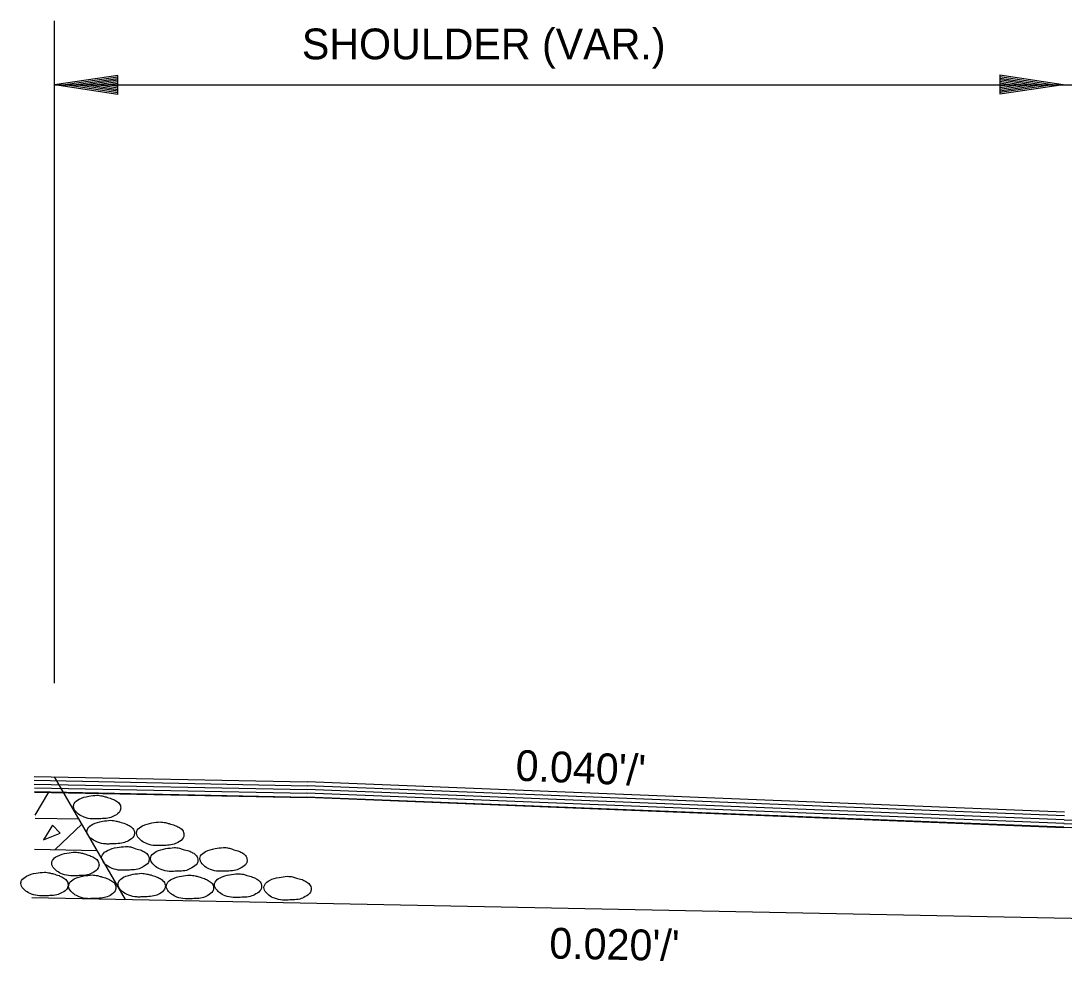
# Model space of a CAD drawing. Extents: x 1926836 to 1933254, y 596317 to 604524.
# Drawn here: x 1928421.2 to 1928623.7, y 602598.8 to 602781.4 of the extents above; entities that cross this region are included whole.
import ezdxf

# ---------------------------------------------------------------- set-up
doc = ezdxf.new("R2010")
doc.units = 0
doc.layers.add('Default', color=7, linetype='Continuous')

msp = doc.modelspace()

# ---------------------------------------------------------------- linework, layer by layer
at = {"layer": 'Default'}
for p, q in [((1928427.69, 602652.78), (1928427.69, 602781.38)), ((1928439.97, 602770.77), (1928427.69, 602768.94)), ((1928439.97, 602770.46), (1928429.75, 602768.94)), ((1928439.97, 602770.14), (1928431.86, 602768.94)), ((1928439.97, 602769.84), (1928433.92, 602768.94)), ((1928439.97, 602769.52), (1928435.98, 602768.94)), ((1928439.97, 602769.21), (1928438.03, 602768.94)), ((1928439.97, 602767.07), (1928439.97, 602770.77)), ((1928611.19, 602770.9), (1928623.46, 602769.03)), ((1928611.19, 602770.9), (1928611.19, 602767.2)), ((1928611.19, 602770.58), (1928621.4, 602769.03)), ((1928611.19, 602770.26), (1928619.3, 602769.03)), ((1928611.19, 602769.97), (1928617.24, 602769.03)), ((1928611.19, 602769.65), (1928615.18, 602769.03)), ((1928611.19, 602769.33), (1928613.12, 602769.03)), ((1928427.69, 602768.94), (1928756.85, 602768.94)), ((1928439.97, 602767.07), (1928427.69, 602768.94)), ((1928439.97, 602767.39), (1928429.75, 602768.94)), ((1928439.97, 602767.71), (1928431.86, 602768.94)), ((1928439.97, 602768.01), (1928433.92, 602768.94)), ((1928439.97, 602768.32), (1928435.98, 602768.94)), ((1928439.97, 602768.64), (1928438.03, 602768.94)), ((1928611.19, 602767.2), (1928623.46, 602769.03)), ((1928611.19, 602768.45), (1928615.18, 602769.03)), ((1928611.19, 602767.83), (1928619.3, 602769.03)), ((1928611.19, 602767.52), (1928621.4, 602769.03)), ((1928611.19, 602768.13), (1928617.24, 602769.03)), ((1928611.19, 602768.77), (1928613.12, 602769.03)), ((1928423.75, 602634.69), (1928476.7, 602633.64)), ((1928423.75, 602633.96), (1928476.7, 602632.9)), ((1928441.46, 602610.8), (1928427.69, 602634.61)), ((1928623.71, 602627.76), (1928476.7, 602633.64)), ((1928423.77, 602633.22), (1928476.7, 602632.17)), ((1928423.8, 602632.49), (1928476.7, 602631.43)), ((1928423.82, 602631.75), (1928476.65, 602630.7)), ((1928423.82, 602631.65), (1928476.7, 602630.6)), ((1928423.92, 602627.19), (1928426.57, 602631.63)), ((1928623.66, 602626.29), (1928476.65, 602632.17)), ((1928623.66, 602625.55), (1928476.65, 602631.43)), ((1928623.71, 602627.02), (1928476.7, 602632.9)), ((1928623.61, 602624.82), (1928476.6, 602630.7)), ((1928623.61, 602624.72), (1928476.7, 602630.6)), ((1928423.95, 602626.61), (1928432.42, 602626.44)), ((1928427.79, 602620.51), (1928433, 602625.43)), ((1928623.61, 602625.55), (1928757.71, 602620.19)), ((1928623.64, 602626.29), (1928757.74, 602620.92)), ((1928623.58, 602624.82), (1928757.68, 602619.45)), ((1928423.82, 602620.59), (1928435.94, 602620.34)), ((1928423.27, 602611.17), (1928815.02, 602603.38))]:
    msp.add_line(p, q, dxfattribs=at)
msp.add_lwpolyline([(1928425.55, 602622.36), (1928428.78, 602623.68), (1928427.31, 602625.25), (1928425.55, 602622.36)], dxfattribs=at)
for points in [[(1928435.93, 602631.06), (1928434.32, 602630.86), (1928432.46, 602630.27), (1928431.52, 602629.44), (1928431.38, 602628.85), (1928431.82, 602627.87), (1928432.36, 602627.38), (1928433.44, 602626.79), (1928435, 602626.45), (1928435.79, 602626.45), (1928437.01, 602626.5), (1928438.34, 602626.65), (1928439.41, 602627.09), (1928440.39, 602627.97), (1928440.54, 602628.56), (1928440.25, 602629.44), (1928439.51, 602630.03), (1928438.78, 602630.37), (1928437.7, 602630.71), (1928436.96, 602630.91), (1928435.93, 602631.06)], [(1928438.6, 602626.19), (1928436.98, 602625.99), (1928435.12, 602625.41), (1928434.14, 602624.57), (1928433.99, 602623.99), (1928434.43, 602623), (1928434.97, 602622.51), (1928436.05, 602621.93), (1928437.62, 602621.58), (1928438.45, 602621.58), (1928439.68, 602621.63), (1928441, 602621.78), (1928442.03, 602622.22), (1928443.06, 602623.1), (1928443.2, 602623.69), (1928442.91, 602624.57), (1928442.17, 602625.16), (1928441.44, 602625.5), (1928440.31, 602625.85), (1928439.63, 602626.04), (1928438.6, 602626.19)], [(1928448.22, 602625.87), (1928446.6, 602625.68), (1928444.74, 602625.09), (1928443.76, 602624.25), (1928443.61, 602623.67), (1928444.05, 602622.69), (1928444.59, 602622.2), (1928445.67, 602621.61), (1928447.24, 602621.27), (1928448.07, 602621.27), (1928449.3, 602621.31), (1928450.62, 602621.46), (1928451.65, 602621.9), (1928452.68, 602622.78), (1928452.82, 602623.37), (1928452.53, 602624.25), (1928451.8, 602624.84), (1928451.06, 602625.19), (1928449.93, 602625.53), (1928449.25, 602625.72), (1928448.22, 602625.87)], [(1928431.72, 602620.01), (1928430.1, 602619.81), (1928428.24, 602619.22), (1928427.31, 602618.39), (1928427.16, 602617.8), (1928427.6, 602616.82), (1928428.14, 602616.33), (1928429.22, 602615.74), (1928430.79, 602615.4), (1928431.57, 602615.4), (1928432.8, 602615.45), (1928434.12, 602615.6), (1928435.2, 602616.04), (1928436.18, 602616.92), (1928436.33, 602617.51), (1928436.03, 602618.39), (1928435.3, 602618.98), (1928434.56, 602619.32), (1928433.48, 602619.66), (1928432.75, 602619.86), (1928431.72, 602620.01)], [(1928441.45, 602621.09), (1928439.83, 602620.9), (1928437.97, 602620.31), (1928436.99, 602619.48), (1928436.84, 602618.94), (1928437.28, 602617.96), (1928437.82, 602617.42), (1928438.9, 602616.83), (1928440.47, 602616.49), (1928441.3, 602616.49), (1928442.53, 602616.54), (1928443.85, 602616.68), (1928444.88, 602617.17), (1928445.91, 602618.01), (1928446.05, 602618.64), (1928445.76, 602619.53), (1928445.02, 602620.11), (1928444.29, 602620.46), (1928443.16, 602620.75), (1928442.48, 602621), (1928441.45, 602621.09)], [(1928450.92, 602620.87), (1928449.3, 602620.68), (1928447.44, 602620.09), (1928446.46, 602619.26), (1928446.32, 602618.72), (1928446.76, 602617.74), (1928447.3, 602617.2), (1928448.37, 602616.61), (1928449.94, 602616.27), (1928450.77, 602616.27), (1928452, 602616.32), (1928453.32, 602616.46), (1928454.35, 602616.95), (1928455.38, 602617.79), (1928455.53, 602618.42), (1928455.23, 602619.31), (1928454.5, 602619.89), (1928453.76, 602620.24), (1928452.64, 602620.53), (1928451.95, 602620.78), (1928450.92, 602620.87)], [(1928460.46, 602620.89), (1928458.84, 602620.69), (1928456.98, 602620.11), (1928456.05, 602619.27), (1928455.9, 602618.73), (1928456.34, 602617.75), (1928456.88, 602617.21), (1928457.96, 602616.63), (1928459.53, 602616.28), (1928460.31, 602616.28), (1928461.54, 602616.33), (1928462.86, 602616.48), (1928463.94, 602616.97), (1928464.92, 602617.8), (1928465.07, 602618.44), (1928464.77, 602619.32), (1928464.04, 602619.91), (1928463.3, 602620.25), (1928462.22, 602620.55), (1928461.49, 602620.79), (1928460.46, 602620.89)], [(1928425.72, 602616.11), (1928424.1, 602615.92), (1928422.24, 602615.33), (1928421.31, 602614.49), (1928421.16, 602613.91), (1928421.6, 602612.93), (1928422.14, 602612.44), (1928423.22, 602611.85), (1928424.79, 602611.51), (1928425.57, 602611.51), (1928426.8, 602611.55), (1928428.12, 602611.7), (1928429.2, 602612.14), (1928430.18, 602613.02), (1928430.32, 602613.61), (1928430.03, 602614.49), (1928429.29, 602615.08), (1928428.56, 602615.43), (1928427.48, 602615.77), (1928426.75, 602615.96), (1928425.72, 602616.11)], [(1928434.99, 602615.58), (1928433.37, 602615.38), (1928431.51, 602614.8), (1928430.58, 602613.96), (1928430.43, 602613.38), (1928430.87, 602612.4), (1928431.41, 602611.91), (1928432.49, 602611.32), (1928434.06, 602610.97), (1928434.84, 602610.97), (1928436.07, 602611.02), (1928437.39, 602611.17), (1928438.47, 602611.61), (1928439.45, 602612.49), (1928439.59, 602613.08), (1928439.3, 602613.96), (1928438.56, 602614.55), (1928437.83, 602614.89), (1928436.75, 602615.24), (1928436.02, 602615.43), (1928434.99, 602615.58)], [(1928444.59, 602615.9), (1928442.97, 602615.7), (1928441.11, 602615.12), (1928440.18, 602614.28), (1928440.03, 602613.69), (1928440.48, 602612.71), (1928441.01, 602612.22), (1928442.09, 602611.64), (1928443.66, 602611.29), (1928444.44, 602611.29), (1928445.67, 602611.34), (1928446.99, 602611.49), (1928448.07, 602611.93), (1928449.05, 602612.81), (1928449.2, 602613.4), (1928448.9, 602614.28), (1928448.17, 602614.87), (1928447.43, 602615.21), (1928446.36, 602615.56), (1928445.62, 602615.75), (1928444.59, 602615.9)], [(1928453.95, 602615.54), (1928452.33, 602615.34), (1928450.47, 602614.76), (1928449.54, 602613.92), (1928449.39, 602613.33), (1928449.84, 602612.35), (1928450.37, 602611.86), (1928451.45, 602611.28), (1928453.02, 602610.93), (1928453.8, 602610.93), (1928455.03, 602610.98), (1928456.35, 602611.13), (1928457.43, 602611.57), (1928458.41, 602612.45), (1928458.56, 602613.04), (1928458.26, 602613.92), (1928457.53, 602614.51), (1928456.79, 602614.85), (1928455.72, 602615.2), (1928454.98, 602615.39), (1928453.95, 602615.54)], [(1928463.29, 602615.8), (1928461.67, 602615.61), (1928459.81, 602615.02), (1928458.88, 602614.18), (1928458.73, 602613.65), (1928459.17, 602612.67), (1928459.71, 602612.13), (1928460.79, 602611.54), (1928462.36, 602611.2), (1928463.14, 602611.2), (1928464.36, 602611.24), (1928465.69, 602611.39), (1928466.77, 602611.88), (1928467.75, 602612.71), (1928467.89, 602613.35), (1928467.6, 602614.23), (1928466.86, 602614.82), (1928466.13, 602615.16), (1928465.05, 602615.46), (1928464.32, 602615.7), (1928463.29, 602615.8)], [(1928472.89, 602615.3), (1928471.27, 602615.1), (1928469.41, 602614.51), (1928468.48, 602613.68), (1928468.33, 602613.14), (1928468.77, 602612.16), (1928469.31, 602611.62), (1928470.39, 602611.03), (1928471.96, 602610.69), (1928472.74, 602610.69), (1928473.97, 602610.74), (1928475.29, 602610.88), (1928476.37, 602611.37), (1928477.35, 602612.21), (1928477.5, 602612.84), (1928477.2, 602613.73), (1928476.47, 602614.32), (1928475.73, 602614.66), (1928474.66, 602614.95), (1928473.92, 602615.2), (1928472.89, 602615.3)]]:
    msp.add_spline(points, degree=3, dxfattribs=at)

# ---------------------------------------------------------------- texts
for s, height, rotation, p in [('SHOULDER (VAR.)', 5.9751, 360, (1928475.7, 602773.92)), ("0.040'/'", 5.975, 357.7094, (1928517.1, 602633.89)), ("0.020'/'", 5.975, 358.8537, (1928523.69, 602599.36))]:
    msp.add_text(s, height=height, rotation=rotation, dxfattribs=at).set_placement(p)

doc.saveas('drawing.dxf')
